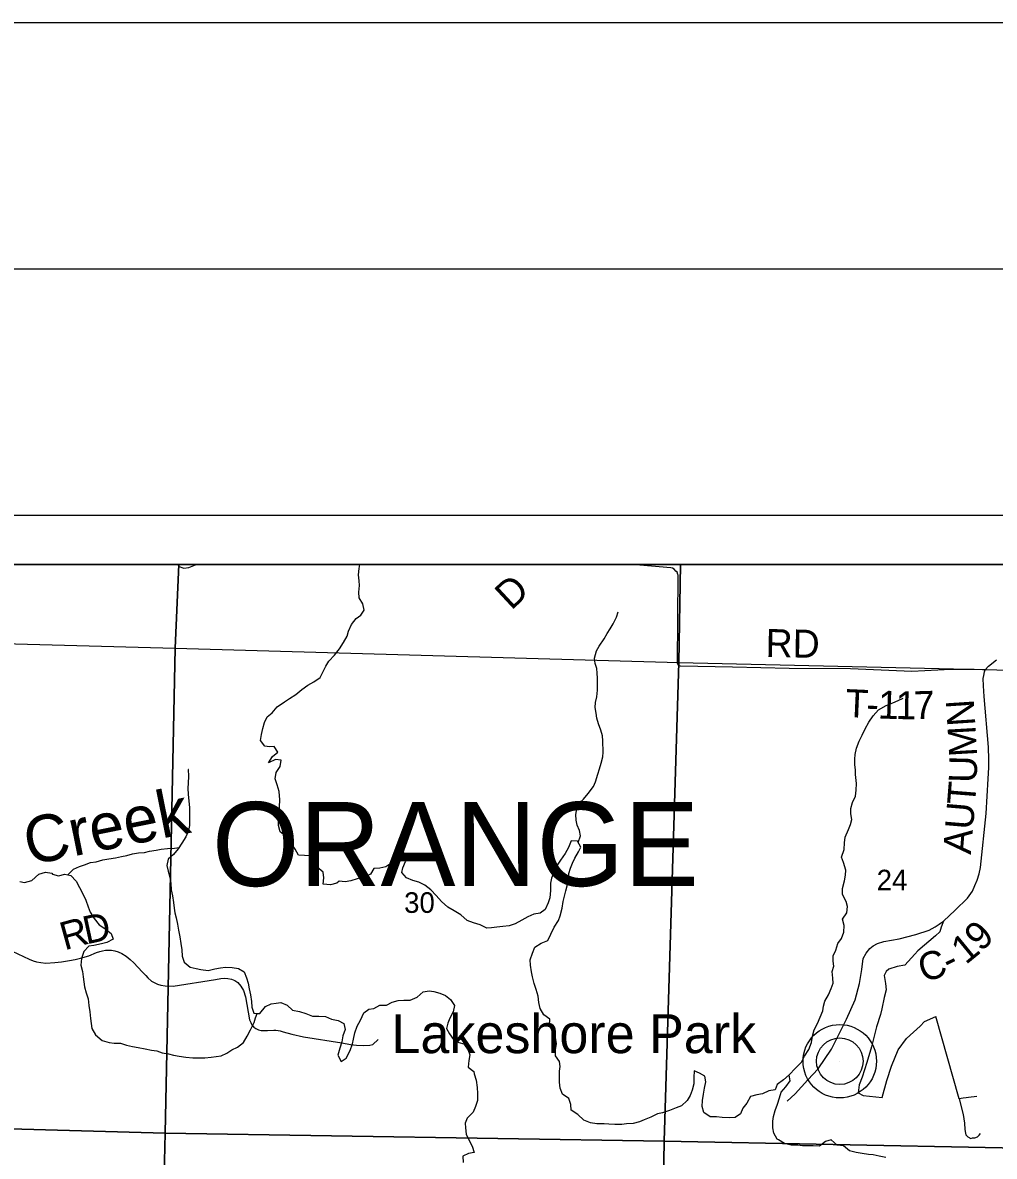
# Model space of a CAD drawing. Extents: x -1.2 to 34, y -8.5 to 22.
# Drawn here: x 6.054 to 8.026, y 19.699 to 22 of the extents above; entities that cross this region are included whole.
import ezdxf

# ---------------------------------------------------------------- set-up
doc = ezdxf.new("R2010")
doc.units = 0
for name, color, linetype in [('Default', 7, 'Continuous'), ('GM_X_County_Road', 7, 'Continuous'), ('GM_X_County_Road_Text', 7, 'Continuous'), ('GM_X_Major_Lake', 7, 'Continuous'), ('GM_X_Major_River', 7, 'Continuous'), ('GM_X_Major_River_Text', 7, 'Continuous'), ('GM_X_Minor_River', 7, 'Continuous'), ('GM_X_Section', 7, 'Continuous'), ('GM_X_Section_Text', 7, 'Continuous'), ('GM_X_Township_Road', 7, 'Continuous'), ('GM_X_Township_Road_Text', 7, 'Continuous'), ('GM_X_Township_Text', 7, 'Continuous'), ('GM_X_Unincorporated', 7, 'Continuous'), ('GM_X_Unincorporated_Location', 7, 'Continuous'), ('GM_X_Unincorporated_Text', 7, 'Continuous'), ('SH_Border', 7, 'Continuous'), ('SH_Cut_Line', 7, 'Continuous'), ('SH_Data', 7, 'Continuous')]:
    doc.layers.add(name, color=color, linetype=linetype)

msp = doc.modelspace()

# ---------------------------------------------------------------- linework, layer by layer
at = {"layer": 'Default'}
msp.add_lwpolyline([(6.3708, 20.9), (5.5189, 20.9), (5.5152, 20.7534), (6.3638, 20.7305)], close=True, dxfattribs=at)
at = {"layer": 'GM_X_County_Road'}
msp.add_lwpolyline([(7.6051, 19.8107), (7.6212, 19.8258), (7.6473, 19.8544), (7.6683, 19.8768), (7.6955, 19.9165), (7.7257, 19.9776), (7.743, 20.0164), (7.7517, 20.0499), (7.7567, 20.078), (7.7595, 20.1002), (7.7655, 20.1114), (7.7728, 20.1204), (7.7797, 20.1261), (7.7887, 20.1308), (7.8014, 20.1348), (7.8323, 20.1404), (7.8666, 20.1493), (7.8934, 20.1582), (7.9058, 20.1646), (7.9139, 20.1702), (7.9224, 20.1761), (7.9464, 20.1984), (7.9712, 20.223), (7.9813, 20.2374), (7.9863, 20.2488), (7.9907, 20.2594), (7.9948, 20.2721), (7.9977, 20.285), (8.0087, 20.3949), (8.0131, 20.465), (8.0147, 20.4882), (8.0142, 20.5045), (8.0138, 20.5295), (8.005, 20.6325), (8.0033, 20.6536), (8.003, 20.6685), (8.0043, 20.6752), (8.0056, 20.6823), (8.0067, 20.6862), (8.0135, 20.6936), (8.0296, 20.7065)], dxfattribs=at)
at = {"layer": 'GM_X_Major_Lake'}
msp.add_line((6.3725, 20.9), (6.3698, 20.8967), dxfattribs=at)
for points in [[(6.3698, 20.8967), (6.3809, 20.8924), (6.3911, 20.8944), (6.4051, 20.8996), (6.4062, 20.9)], [(6.5505, 20.5913), (6.5603, 20.599), (6.5707, 20.611), (6.5857, 20.6214), (6.5959, 20.6281), (6.6087, 20.6366), (6.6207, 20.6463), (6.6327, 20.6552), (6.6451, 20.6619), (6.6575, 20.6708), (6.6623, 20.6804), (6.6693, 20.6938), (6.6756, 20.7037), (6.6872, 20.7161), (6.6972, 20.7287), (6.7054, 20.7421), (6.7128, 20.7544), (6.7156, 20.7651), (6.7211, 20.7781), (6.7308, 20.7907), (6.7406, 20.797), (6.7468, 20.8077), (6.7447, 20.8206), (6.7369, 20.8326), (6.736, 20.8443), (6.7373, 20.8576), (6.7371, 20.8671), (6.7358, 20.8792), (6.7367, 20.8921), (6.7381, 20.9)], [(6.6919, 20.2533), (6.679, 20.2497), (6.6642, 20.2514), (6.6651, 20.2639), (6.6637, 20.276), (6.6518, 20.2857), (6.6455, 20.2973), (6.6377, 20.3086), (6.6263, 20.3095), (6.6141, 20.3105), (6.6071, 20.3221), (6.5989, 20.3345), (6.5892, 20.3472), (6.5769, 20.3573), (6.5732, 20.3701), (6.573, 20.3838), (6.5739, 20.3955), (6.5752, 20.4085), (6.5758, 20.4225), (6.5747, 20.4392), (6.5703, 20.4528), (6.5667, 20.4652), (6.5688, 20.4782), (6.5765, 20.4904), (6.5786, 20.503), (6.5672, 20.5043), (6.5528, 20.4976), (6.561, 20.5107), (6.5722, 20.5192), (6.5648, 20.5308), (6.5553, 20.5299), (6.5454, 20.5313), (6.5369, 20.5429), (6.5386, 20.5551), (6.5418, 20.5672), (6.545, 20.5798), (6.5505, 20.5913)], [(6.3904, 20.484), (6.39, 20.4839), (6.391, 20.4703), (6.3897, 20.4563), (6.3891, 20.446), (6.3897, 20.4331), (6.3911, 20.4202), (6.3924, 20.4062), (6.3926, 20.3933), (6.3925, 20.3804), (6.3926, 20.3706), (6.3909, 20.3603), (6.385, 20.3473), (6.3773, 20.3347), (6.3699, 20.3231), (6.3602, 20.3112), (6.3493, 20.3023), (6.3469, 20.289), (6.3497, 20.2777), (6.3526, 20.2652), (6.3551, 20.2527), (6.3557, 20.2398), (6.3585, 20.2274), (6.3603, 20.2141), (6.3616, 20.2028), (6.3629, 20.1929), (6.3657, 20.1831), (6.3682, 20.1702), (6.3707, 20.1578), (6.3732, 20.1441), (6.3754, 20.1309), (6.3771, 20.118), (6.3781, 20.1055), (6.3821, 20.0927), (6.394, 20.0826), (6.4062, 20.0802), (6.4158, 20.0781), (6.4306, 20.0764), (6.4439, 20.0797), (6.4556, 20.0814), (6.4659, 20.0827), (6.4796, 20.0822), (6.4922, 20.0801), (6.5033, 20.0731), (6.5081, 20.061), (6.5117, 20.0504), (6.5138, 20.0387), (6.5166, 20.0266), (6.5184, 20.0134), (6.5189, 20.0016), (6.5233, 19.9892), (6.5297, 19.9889)], [(7.1806, 19.7841), (7.1671, 19.7926), (7.1666, 19.8044), (7.1622, 19.8165), (7.1495, 19.825), (7.1447, 19.8374), (7.1434, 19.8492), (7.1432, 19.8613), (7.1434, 19.8719), (7.1444, 19.8814), (7.1435, 19.8913), (7.1353, 19.9029), (7.1355, 19.9147), (7.1372, 19.9272), (7.1354, 19.9401), (7.1299, 19.9514), (7.1232, 19.9645), (7.1238, 19.9771), (7.1118, 19.986), (7.1044, 19.9991), (7.1015, 20.0112), (7.0998, 20.0241), (7.0962, 20.0373), (7.0922, 20.0497), (7.0889, 20.0633), (7.0868, 20.0732), (7.0843, 20.0868), (7.0841, 20.0974), (7.0885, 20.1111), (7.0936, 20.1237), (7.1064, 20.1315), (7.1196, 20.1371), (7.1255, 20.1501), (7.1328, 20.1642), (7.141, 20.1773), (7.1446, 20.1872), (7.1485, 20.2024), (7.151, 20.2161), (7.1534, 20.2272), (7.1559, 20.2378), (7.1595, 20.2504), (7.1613, 20.2599), (7.1626, 20.2732), (7.1658, 20.2835), (7.1698, 20.2942), (7.1746, 20.3041), (7.1816, 20.3168), (7.1868, 20.3263), (7.1797, 20.3384), (7.1672, 20.3393), (7.1613, 20.3259), (7.155, 20.3137), (7.1454, 20.3002), (7.1376, 20.2876), (7.1317, 20.2754), (7.127, 20.2635), (7.1249, 20.2536), (7.1251, 20.2384), (7.1235, 20.2236), (7.1206, 20.2133), (7.114, 20.1996), (7.1038, 20.1922), (7.091, 20.1901), (7.0789, 20.1853), (7.0668, 20.1783), (7.0536, 20.1709), (7.0415, 20.1669), (7.0286, 20.1652), (7.0165, 20.1642), (7.0051, 20.1625), (6.9956, 20.162), (6.9826, 20.169), (6.9688, 20.1729), (6.9562, 20.1776), (6.9435, 20.1888), (6.9296, 20.1973), (6.917, 20.2047), (6.9042, 20.2162), (6.8934, 20.2286), (6.8826, 20.2398), (6.8699, 20.249), (6.8583, 20.2553), (6.8457, 20.2589), (6.8327, 20.264), (6.8238, 20.2748), (6.8252, 20.2843), (6.831, 20.2973), (6.8384, 20.3104), (6.8285, 20.314), (6.8149, 20.3054), (6.8052, 20.2962), (6.7913, 20.2868), (6.7788, 20.284), (6.767, 20.283), (6.7596, 20.2715), (6.7468, 20.2652), (6.7328, 20.2623), (6.7199, 20.2583), (6.7086, 20.2563), (6.6964, 20.2576), (6.6919, 20.2533)], [(6.5297, 19.9889), (6.5355, 19.9886), (6.547, 20.0032), (6.5587, 20.0083), (6.5682, 20.01), (6.5777, 20.0109), (6.5911, 20.0055), (6.6019, 19.9958), (6.6156, 19.993), (6.629, 19.989), (6.6424, 19.9832), (6.6549, 19.9834), (6.6683, 19.9824), (6.6805, 19.977), (6.6942, 19.9749), (6.7061, 19.9687), (6.7082, 19.9566), (6.7035, 19.9436), (6.7018, 19.931), (6.6979, 19.9181), (6.6939, 19.9043), (6.7002, 19.8912), (6.7107, 19.8978), (6.7185, 19.9138), (6.7236, 19.9272), (6.7253, 19.9367), (6.7281, 19.9493), (6.7332, 19.963), (6.7399, 19.9753), (6.7465, 19.9898), (6.7562, 19.9976), (6.7665, 19.9989), (6.7789, 20.0055), (6.7922, 20.0057), (6.8039, 20.0116), (6.816, 20.0152), (6.8278, 20.0158), (6.8407, 20.0156), (6.8546, 20.0219), (6.867, 20.0331), (6.8791, 20.0345), (6.8887, 20.0335), (6.9005, 20.0299), (6.9124, 20.0255), (6.9224, 20.0174), (6.9302, 20.005), (6.9274, 19.992), (6.9211, 19.9794), (6.9167, 19.9695), (6.9143, 19.958), (6.9201, 19.9475)], [(6.9201, 19.9475), (6.9283, 19.9359), (6.9394, 19.93), (6.949, 19.9271), (6.9579, 19.9144), (6.9615, 19.9046), (6.9594, 19.8932), (6.9578, 19.8799), (6.9697, 19.8709)], [(6.9697, 19.8709), (6.9705, 19.866), (6.9745, 19.8532), (6.9763, 19.8388), (6.9769, 19.8263), (6.9768, 19.8119), (6.9731, 19.8001), (6.968, 19.7886), (6.9557, 19.7766), (6.952, 19.7663), (6.9526, 19.7568), (6.9543, 19.744), (6.9594, 19.7323), (6.9665, 19.7195), (6.9705, 19.7067), (6.9584, 19.7046), (6.9474, 19.6995), (6.9477, 19.6866)], [(7.5848, 19.7336), (7.5781, 19.7456), (7.576, 19.7566), (7.5762, 19.7702), (7.5772, 19.7797), (7.5811, 19.7919), (7.5855, 19.8049), (7.5898, 19.8175), (7.5931, 19.8289), (7.6028, 19.8401), (7.6113, 19.852), (7.6096, 19.8645), (7.598, 19.8544), (7.5848, 19.8447), (7.5812, 19.8337), (7.5683, 19.8319), (7.5555, 19.826), (7.5434, 19.8239), (7.5309, 19.8203), (7.5235, 19.8065), (7.5153, 19.7969), (7.5109, 19.7854), (7.5, 19.7777), (7.4875, 19.7771), (7.4734, 19.7776), (7.4616, 19.7789), (7.4487, 19.7787), (7.436, 19.7876), (7.4331, 19.8001), (7.4337, 19.8122), (7.4354, 19.8252), (7.4375, 19.8373), (7.4403, 19.8503), (7.4382, 19.8616), (7.4271, 19.8679), (7.4163, 19.8723), (7.4158, 19.859), (7.416, 19.8461), (7.4128, 19.8331), (7.4084, 19.8224), (7.4025, 19.8125), (7.3909, 19.8017), (7.38, 19.7973), (7.3664, 19.7921), (7.3524, 19.7874), (7.3425, 19.7849), (7.3286, 19.7782), (7.3154, 19.7727), (7.3055, 19.7691), (7.2927, 19.7655), (7.2794, 19.7649), (7.2695, 19.7636), (7.2558, 19.7634), (7.2433, 19.7643), (7.2338, 19.7649), (7.2193, 19.7651), (7.2064, 19.7667), (7.193, 19.7722), (7.1806, 19.7841)], [(7.8051, 19.6966), (7.7922, 19.6995), (7.7796, 19.7019), (7.77, 19.7029), (7.7575, 19.7046), (7.7453, 19.7066), (7.7315, 19.7102), (7.7196, 19.7199), (7.7066, 19.7212), (7.6947, 19.7324), (7.6829, 19.7291), (7.6709, 19.7194), (7.658, 19.72), (7.6458, 19.7205), (7.6363, 19.7204), (7.6268, 19.7214), (7.6135, 19.7215), (7.6001, 19.7251), (7.5875, 19.7325), (7.5848, 19.7336)]]:
    msp.add_lwpolyline(points, dxfattribs=at)
at = {"layer": 'GM_X_Major_River'}
for points in [[(6.0486, 20.2564), (6.0582, 20.2547), (6.0725, 20.2587), (6.0868, 20.2718), (6.1004, 20.2758), (6.1137, 20.2738)], [(6.1137, 20.2738), (6.1145, 20.2719), (6.1271, 20.2679), (6.14, 20.2716), (6.1522, 20.2687), (6.163, 20.2571), (6.1697, 20.2447), (6.1764, 20.2316), (6.1827, 20.2188), (6.1871, 20.2056), (6.1915, 20.1943), (6.1993, 20.1815), (6.2094, 20.1691), (6.2209, 20.1614), (6.234, 20.1513), (6.2376, 20.1396), (6.2252, 20.133), (6.2142, 20.1305), (6.1987, 20.1269), (6.1888, 20.1256), (6.1783, 20.1144), (6.1736, 20.1006), (6.1723, 20.087), (6.1756, 20.0737), (6.1773, 20.0631), (6.1786, 20.0533), (6.1799, 20.0431), (6.1832, 20.0306), (6.1868, 20.0185), (6.1885, 20.0049), (6.1903, 19.9924), (6.1916, 19.9784), (6.1933, 19.9686), (6.1946, 19.9583), (6.2017, 19.9452), (6.2156, 19.9337), (6.2297, 19.9301), (6.24, 19.9287), (6.2529, 19.9286), (6.2648, 19.9246), (6.277, 19.9221), (6.2888, 19.9201), (6.3025, 19.9173), (6.3155, 19.9144), (6.3262, 19.9127), (6.3373, 19.9091), (6.3498, 19.907), (6.3601, 19.9045), (6.372, 19.9021), (6.3853, 19.9004), (6.3994, 19.8987), (6.4123, 19.8986), (6.4241, 19.8988), (6.437, 19.9001), (6.4469, 19.9014), (6.4567, 19.9031), (6.4684, 19.9082), (6.4789, 19.9148), (6.4903, 19.9203), (6.5023, 19.9296), (6.51, 19.943), (6.5167, 19.9557), (6.524, 19.9702), (6.5269, 19.9797), (6.5297, 19.9889)]]:
    msp.add_lwpolyline(points, dxfattribs=at)
at = {"layer": 'GM_X_Minor_River'}
for points in [[(7.181, 20.3361), (7.1857, 20.3493), (7.1841, 20.3603), (7.1794, 20.3713), (7.1774, 20.3815), (7.1765, 20.3929), (7.1784, 20.4039), (7.1817, 20.4141), (7.1922, 20.4237), (7.2016, 20.4352), (7.2125, 20.4493), (7.2162, 20.4592), (7.221, 20.4748), (7.2244, 20.4854), (7.2277, 20.4972), (7.2314, 20.5098), (7.2317, 20.5193), (7.2315, 20.5424), (7.2306, 20.5526), (7.2271, 20.564), (7.2224, 20.5768), (7.2193, 20.5886), (7.218, 20.5981), (7.2157, 20.6098), (7.2163, 20.6204), (7.2193, 20.6318), (7.2207, 20.6451), (7.2205, 20.6694), (7.22, 20.6796), (7.2191, 20.6891), (7.216, 20.6993), (7.2144, 20.7099), (7.2181, 20.7248), (7.2237, 20.7347), (7.2342, 20.7495), (7.2398, 20.7602), (7.2462, 20.7698), (7.2525, 20.78), (7.2592, 20.7934), (7.2622, 20.8044)], [(7.6096, 19.8645), (7.6221, 19.8777), (7.6341, 19.8903), (7.6401, 19.9021), (7.6495, 19.9158), (7.6543, 19.9299), (7.6565, 19.9428), (7.6598, 19.9554), (7.6665, 19.9687), (7.6725, 19.9813), (7.6773, 19.9942), (7.6791, 20.0037), (7.6817, 20.0136), (7.6892, 20.0266), (7.6947, 20.0392), (7.6988, 20.0506), (7.6976, 20.0604), (7.6967, 20.0741), (7.7, 20.0847), (7.6988, 20.095), (7.6983, 20.1056), (7.7043, 20.1174), (7.708, 20.1307), (7.7155, 20.141), (7.7199, 20.1539), (7.7206, 20.1672), (7.7178, 20.1801), (7.7261, 20.1931), (7.7275, 20.206), (7.7251, 20.2158), (7.7174, 20.2305), (7.7176, 20.2427), (7.7213, 20.2583), (7.7239, 20.2697), (7.7242, 20.2799), (7.7198, 20.2951), (7.7156, 20.3064), (7.7211, 20.3216), (7.7218, 20.3349), (7.7228, 20.3467), (7.7295, 20.3623), (7.734, 20.3722), (7.7365, 20.3824), (7.7345, 20.3942), (7.7341, 20.4052), (7.7381, 20.417), (7.7437, 20.4299), (7.7455, 20.4421), (7.7458, 20.4557), (7.7437, 20.4736), (7.7436, 20.4834), (7.7424, 20.4936), (7.7423, 20.505), (7.7434, 20.5145), (7.7459, 20.5274), (7.7515, 20.5415), (7.7575, 20.5537), (7.7634, 20.5663), (7.7709, 20.58), (7.7795, 20.593), (7.7908, 20.6052), (7.8063, 20.6141), (7.8199, 20.6191), (7.8305, 20.6238), (7.8404, 20.6288)], [(6.1457, 20.2702), (6.1573, 20.2819), (6.1697, 20.2873), (6.1796, 20.2904), (6.1921, 20.2951), (6.2031, 20.2967), (6.2167, 20.3006), (6.2289, 20.303), (6.2429, 20.3046), (6.255, 20.3074), (6.2656, 20.3093), (6.277, 20.3129), (6.2895, 20.3149), (6.3017, 20.3157), (6.3115, 20.3185), (6.3248, 20.3205), (6.335, 20.3225), (6.3483, 20.3237), (6.362, 20.3246), (6.3717, 20.3259)]]:
    msp.add_lwpolyline(points, dxfattribs=at)
at = {"layer": 'GM_X_Section'}
for points in [[(7.3889, 20.9), (6.3708, 20.9), (6.3638, 20.7305), (7.3857, 20.701)], [(8.4165, 20.9), (7.3889, 20.9), (7.3857, 20.701), (8.4117, 20.6773)], [(5.5152, 20.7534), (6.3638, 20.7305), (6.3436, 19.7459), (5.4939, 19.7699), (5.5138, 20.6632)], [(6.3638, 20.7305), (7.3857, 20.701), (7.3559, 19.7295), (6.3436, 19.7459)], [(7.3857, 20.701), (8.4117, 20.6773), (8.3845, 19.7092), (7.3559, 19.7295)], [(5.4939, 19.7699), (6.3436, 19.7459), (6.3194, 18.751), (5.4804, 18.7665), (5.4956, 19.6725)], [(6.3436, 19.7459), (7.3559, 19.7295), (7.3389, 18.7336), (6.3194, 18.751)], [(8.3845, 19.7092), (8.3694, 18.7126), (7.3389, 18.7336), (7.3559, 19.7295)]]:
    msp.add_lwpolyline(points, close=True, dxfattribs=at)
at = {"layer": 'GM_X_Township_Road'}
for points in [[(8.0067, 20.6862), (7.9846, 20.6871), (7.9374, 20.6871), (7.8583, 20.6829), (7.734, 20.6887), (7.6094, 20.6892), (7.4946, 20.6915), (7.3887, 20.6937), (7.387, 20.6943), (7.3852, 20.6955), (7.3832, 20.6979), (7.3825, 20.7), (7.3838, 20.8784), (7.3835, 20.8801), (7.3819, 20.8844), (7.3795, 20.8869), (7.3758, 20.8904), (7.3724, 20.8924), (7.3695, 20.8936), (7.2909, 20.9)], [(7.9224, 20.1761), (7.9179, 20.1638), (7.9152, 20.1545), (7.9059, 20.1462), (7.8706, 20.1158), (7.8645, 20.1091)], [(6.0329, 20.1153), (6.0677, 20.0989), (6.0754, 20.096), (6.0822, 20.0938), (6.0909, 20.0921), (6.1011, 20.0909), (6.1194, 20.0921), (6.1329, 20.0934), (6.149, 20.0962), (6.1608, 20.0985), (6.1716, 20.1009), (6.1888, 20.1061), (6.2041, 20.1125), (6.2105, 20.1144), (6.216, 20.1162), (6.2224, 20.1174), (6.2285, 20.1176), (6.2344, 20.1174), (6.2414, 20.116), (6.2479, 20.1137), (6.2552, 20.1104), (6.2639, 20.1051), (6.2723, 20.0986), (6.2795, 20.0917), (6.2965, 20.0736), (6.3041, 20.0656), (6.3083, 20.0609), (6.3154, 20.0546), (6.3212, 20.0514), (6.3279, 20.0484), (6.3345, 20.0463), (6.3435, 20.0447), (6.3596, 20.0444), (6.4456, 20.0581), (6.4563, 20.0595), (6.4637, 20.0603), (6.4703, 20.0598), (6.4782, 20.0584), (6.4846, 20.0557), (6.4906, 20.0514), (6.4969, 20.0446), (6.502, 20.0358), (6.5062, 20.0227), (6.5146, 19.976), (6.5169, 19.9703), (6.5195, 19.9657), (6.5231, 19.9611), (6.5272, 19.9581), (6.5328, 19.9555), (6.5383, 19.9546), (6.5507, 19.9543), (6.5635, 19.9551), (6.5681, 19.955), (6.5724, 19.9544), (6.5768, 19.9533), (6.5825, 19.9516), (6.6002, 19.9466), (6.6243, 19.9412), (6.7015, 19.929), (6.7191, 19.9257), (6.7318, 19.9246), (6.7456, 19.9236), (6.7586, 19.9244), (6.7645, 19.9257), (6.7755, 19.936)], [(7.8645, 20.1091), (7.844, 20.0869), (7.8286, 20.0842), (7.8115, 20.0787), (7.8059, 20.0737), (7.8019, 20.0662), (7.8049, 20.05), (7.8062, 20.0366), (7.8022, 20.0211), (7.7976, 19.9984), (7.7943, 19.987)], [(7.7943, 19.987), (7.7868, 19.9616), (7.7766, 19.9212), (7.7671, 19.8893), (7.7572, 19.8593), (7.7516, 19.8442), (7.7493, 19.8278), (7.7595, 19.8222), (7.7983, 19.8182)], [(7.7983, 19.8182), (7.8072, 19.8528), (7.817, 19.8817), (7.8305, 19.9152), (7.8473, 19.9383), (7.8618, 19.9511), (7.8752, 19.9629), (7.8838, 19.9724), (7.9068, 19.9826)], [(7.9903, 19.8205), (7.9732, 19.8186), (7.9683, 19.8179), (7.9621, 19.8169), (7.9542, 19.8159), (7.9068, 19.9826)], [(7.9542, 19.8159), (7.9624, 19.7837), (7.9647, 19.766), (7.9658, 19.753), (7.9668, 19.7461), (7.9678, 19.7424), (7.9721, 19.7382), (7.9778, 19.7352), (7.9812, 19.7362), (7.9859, 19.7367), (7.9911, 19.7387), (7.9951, 19.7418), (7.9977, 19.7449)]]:
    msp.add_lwpolyline(points, dxfattribs=at)
at = {"layer": 'GM_X_Unincorporated'}
for radius in [0.0744, 0.0472]:
    msp.add_circle((7.712, 19.8919), radius, dxfattribs=at)
at = {"layer": 'GM_X_Unincorporated_Location'}
msp.add_line((7.712, 19.8919), (7.712, 19.8919), dxfattribs=at)
at = {"layer": 'GM_X_Unincorporated_Text'}
msp.add_lwpolyline([(6.665, 17.7216), (6.6751, 17.7216), (6.7322, 17.7204), (7.1254, 17.7122), (7.3722, 17.707), (7.8111, 17.6977), (7.9782, 17.6941), (8.3326, 17.6871), (8.3461, 18.0704), (8.364, 18.7117), (8.3686, 18.968), (8.382, 19.7108), (8.4089, 20.6815), (8.4143, 20.9), (2.465, 20.9)], dxfattribs=at)
at = {"layer": 'SH_Border'}
msp.add_lwpolyline([(1.5, 21.5), (33.5, 21.5), (33.5, 0.5), (1.5, 0.5)], close=True, dxfattribs=at)
at = {"layer": 'SH_Cut_Line'}
msp.add_lwpolyline([(0, 0), (34, 0), (34, 22), (0, 22)], close=True, dxfattribs=at)
msp.add_lwpolyline([(6.665, 17.7216), (6.6751, 17.7216), (6.7322, 17.7204), (7.1254, 17.7122), (7.3722, 17.707), (7.8111, 17.6977), (7.9782, 17.6941), (8.3326, 17.6871), (8.9, 17.6758), (8.9, 20.9), (2.465, 20.9)], dxfattribs=at)
at = {"layer": 'SH_Data'}
for p, q in [((2, 21), (9, 21)), ((2.1, 20.9), (8.9, 20.9))]:
    msp.add_line(p, q, dxfattribs=at)

# ---------------------------------------------------------------- texts
at = {"layer": 'GM_X_County_Road_Text'}
for s, rotation, p in [('N', 93.7532, (7.9872, 20.5735)), ('M', 93.2844, (7.9908, 20.5114)), ('U', 88.7388, (7.9898, 20.4565)), ('T', 85.4755, (7.9862, 20.4106)), ('U', 85.2261, (7.982, 20.3605)), ('A', 85.2297, (7.9779, 20.3107)), ('9', 44.1561, (7.9985, 20.1124)), ('1', 39.3224, (7.9676, 20.0867)), ('C', 17.687, (7.8817, 20.0512)), ('-', 26.0766, (7.9346, 20.0687))]:
    msp.add_text(s, height=0.0568, rotation=rotation, dxfattribs=at).set_placement(p)
at = {"layer": 'GM_X_Major_River_Text'}
msp.add_text('Creek', height=0.0947, rotation=11.4091, dxfattribs=at).set_placement((6.0671, 20.2894))
at = {"layer": 'GM_X_Section_Text'}
for s, p in [('24', (7.7868, 20.2387)), ('30', (6.8281, 20.193))]:
    msp.add_text(s, height=0.04186, rotation=0, dxfattribs=at).set_placement(p)
at = {"layer": 'GM_X_Township_Road_Text'}
for s, height, rotation, p in [('D', 0.0568, 42.8577, (7.0454, 20.8059)), ('RD', 0.05682, 359.0293, (7.5611, 20.7125)), ('T', 0.0568, 357.4727, (7.7224, 20.5907)), ('1', 0.0568, 357.9312, (7.7887, 20.5878)), ('1', 0.0568, 358.9515, (7.8248, 20.5865)), ('7', 0.0568, 1.7317, (7.8628, 20.5859)), ('-', 0.0568, 357.5755, (7.765, 20.5888)), ('R', 0.0568, 15.4961, (6.1392, 20.1167)), ('D', 0.0568, 12.208, (6.1833, 20.1289))]:
    msp.add_text(s, height=height, rotation=rotation, dxfattribs=at).set_placement(p)
at = {"layer": 'GM_X_Township_Text'}
msp.add_text('ORANGE', height=0.17045, rotation=0, dxfattribs=at).set_placement((6.4384, 20.2475))
at = {"layer": 'GM_X_Unincorporated_Text'}
msp.add_text('Lakeshore Park', height=0.078977, rotation=0, dxfattribs=at).set_placement((6.8026, 19.9083))

doc.saveas('drawing.dxf')
